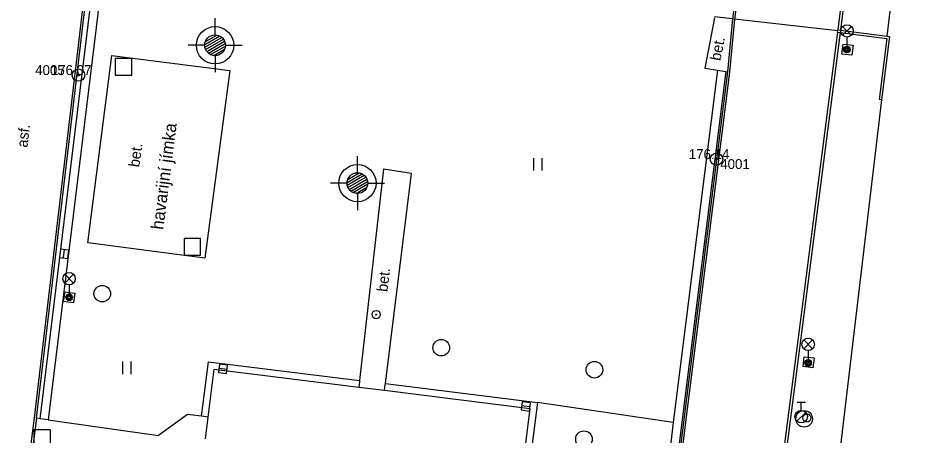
# Model space of a CAD drawing. Extents: x -540235 to -537963, y -1184915 to -1183660.
# Drawn here: x -540130.4 to -540075.6, y -1184027.1 to -1184001.9 of the extents above; entities that cross this region are included whole.
import ezdxf

# ---------------------------------------------------------------- set-up
doc = ezdxf.new("R2010")
doc.units = 0
for name, color, linetype in [('Vrstva 10', 7, 'Continuous'), ('Vrstva 11', 7, 'Continuous'), ('Vrstva 21', 7, 'Continuous'), ('Vrstva 22', 7, 'Continuous'), ('Vrstva 23', 7, 'Continuous'), ('Vrstva 25', 7, 'Continuous'), ('Vrstva 26', 7, 'Continuous'), ('Vrstva 27', 7, 'Continuous'), ('Vrstva 28', 7, 'Continuous'), ('Vrstva 33', 7, 'Continuous'), ('Vrstva 35', 7, 'Continuous'), ('Vrstva 36', 7, 'Continuous'), ('Vrstva 40', 7, 'Continuous'), ('Vrstva 41', 7, 'Continuous'), ('Vrstva 5', 7, 'Continuous'), ('Vrstva 7', 7, 'Continuous'), ('Vrstva 8', 7, 'Continuous')]:
    doc.layers.add(name, color=color, linetype=linetype)

msp = doc.modelspace()

# ---------------------------------------------------------------- linework, layer by layer
at = {"layer": 'Vrstva 10'}
for p, q in [((-540078.46, -1183982.89), (-540080.947, -1184002.636)), ((-540129.3, -1184026.075), (-540126.08, -1183998.755)), ((-540080.966, -1184002.785), (-540086.04, -1184042.215)), ((-540087.61, -1184005.175), (-540090.57, -1184028.685))]:
    msp.add_line(p, q, dxfattribs=at)
msp.add_lwpolyline([(-540085.41, -1183988), (-540087.303, -1184001.976), (-540087.61, -1184005.175)], dxfattribs=at)
at = {"layer": 'Vrstva 11'}
for p, q in [((-540129.419, -1184026.061), (-540126.213, -1183998.856)), ((-540129.092, -1184026.105), (-540125.768, -1183998.87)), ((-540125.272, -1183998.93), (-540128.597, -1184026.175)), ((-540080.428, -1183999.778), (-540080.798, -1184002.655)), ((-540080.818, -1184002.804), (-540085.892, -1184042.238)), ((-540126.21, -1184015.5), (-540124.76, -1184004.18)), ((-540124.76, -1184004.18), (-540117.65, -1184005.09)), ((-540117.65, -1184005.09), (-540119.15, -1184016.42)), ((-540088.203, -1184005.08), (-540090.879, -1184026.337)), ((-540087.709, -1184005.159), (-540090.669, -1184028.669)), ((-540087.491, -1184005.188), (-540090.451, -1184028.703)), ((-540108.36, -1184011.05), (-540109.813, -1184023.807)), ((-540106.68, -1184011.3), (-540108.36, -1184011.05)), ((-540108.25, -1184023.989), (-540106.68, -1184011.3)), ((-540119.15, -1184016.42), (-540126.21, -1184015.5)), ((-540119.356, -1184025.955), (-540118.93, -1184022.67)), ((-540118.93, -1184022.67), (-540109.813, -1184023.807)), ((-540108.25, -1184023.989), (-540099.08, -1184025.12)), ((-540099.08, -1184025.12), (-540099.851, -1184031.26)), ((-540129.936, -1184029.955), (-540129.419, -1184026.061)), ((-540129.3, -1184026.075), (-540129.817, -1184029.971)), ((-540128.597, -1184026.175), (-540121.94, -1184027.125)), ((-540090.879, -1184026.337), (-540091.163, -1184028.593))]:
    msp.add_line(p, q, dxfattribs=at)
for points in [[(-540086.777, -1183999.027), (-540087.183, -1184001.991), (-540087.491, -1184005.188)], [(-540088.4, -1184001.925), (-540088.98, -1184004.955), (-540088.203, -1184005.08), (-540087.709, -1184005.159), (-540087.61, -1184005.175)], [(-540080.701, -1184004.098), (-540080.629, -1184003.502), (-540080.033, -1184003.574), (-540080.105, -1184004.17), (-540080.701, -1184004.098)], [(-540127.58, -1184018.44), (-540126.987, -1184018.529), (-540127.076, -1184019.122), (-540127.669, -1184019.033), (-540127.58, -1184018.44)], [(-540083.051, -1184022.959), (-540082.979, -1184022.363), (-540082.383, -1184022.435), (-540082.455, -1184023.03), (-540083.051, -1184022.959)], [(-540109.813, -1184023.807), (-540109.82, -1184023.87), (-540109.86, -1184024.195)], [(-540108.3, -1184024.39), (-540108.26, -1184024.07), (-540108.25, -1184023.989)], [(-540118.952, -1184026.008), (-540119.356, -1184025.955), (-540120.19, -1184025.845), (-540121.94, -1184027.125)], [(-540128.597, -1184026.175), (-540129.092, -1184026.105), (-540129.3, -1184026.075)]]:
    msp.add_lwpolyline(points, dxfattribs=at)
at = {"layer": 'Vrstva 21'}
for centre, radius in [((-540126.77, -1184005.37), 0.375), ((-540126.77, -1184005.37), 0.05), ((-540088.27, -1184010.44), 0.375), ((-540088.27, -1184010.44), 0.05)]:
    msp.add_circle(centre, radius, dxfattribs=at)
at = {"layer": 'Vrstva 23'}
msp.add_line((-540090.879, -1184026.337), (-540099.08, -1184025.12), dxfattribs=at)
at = {"layer": 'Vrstva 25'}
for radius in [0.25, 0.0303]:
    msp.add_circle((-540108.81, -1184019.82), radius, dxfattribs=at)
at = {"layer": 'Vrstva 26'}
for points in [[(-540124.55, -1184005.372), (-540123.55, -1184005.372), (-540123.55, -1184004.372), (-540124.55, -1184004.372)], [(-540120.405, -1184016.232), (-540119.405, -1184016.232), (-540119.405, -1184015.232), (-540120.405, -1184015.232)], [(-540129.46, -1184027.775), (-540128.46, -1184027.775), (-540128.46, -1184026.775), (-540129.46, -1184026.775)]]:
    msp.add_lwpolyline(points, close=True, dxfattribs=at)
at = {"layer": 'Vrstva 27'}
for p, q in [((-540127.67, -1184016.398), (-540127.61, -1184015.902)), ((-540117.802, -1184023.131), (-540118.298, -1184023.069)), ((-540099.532, -1184025.391), (-540100.028, -1184025.329))]:
    msp.add_line(p, q, dxfattribs=at)
for points in [[(-540127.422, -1184016.428), (-540127.362, -1184015.932), (-540127.858, -1184015.872), (-540127.918, -1184016.368)], [(-540117.771, -1184022.883), (-540118.267, -1184022.821), (-540118.329, -1184023.317), (-540117.833, -1184023.379)], [(-540099.501, -1184025.143), (-540099.997, -1184025.081), (-540100.059, -1184025.577), (-540099.563, -1184025.639)]]:
    msp.add_lwpolyline(points, close=True, dxfattribs=at)
for centre in [(-540125.34, -1184018.56), (-540104.88, -1184021.82), (-540095.64, -1184023.15), (-540082.98, -1184026.11), (-540096.27, -1184027.34)]:
    msp.add_circle(centre, 0.5, dxfattribs=at)
at = {"layer": 'Vrstva 28'}
for p, q in [((-540083.41, -1184025.105), (-540082.91, -1184025.105)), ((-540083.16, -1184025.605), (-540083.16, -1184025.105)), ((-540083.418, -1184026.252), (-540082.888, -1184025.722))]:
    msp.add_line(p, q, dxfattribs=at)
for centre, radius in [((-540083.16, -1184025.98), 0.375), ((-540082.82, -1184026.06), 0.25)]:
    msp.add_circle(centre, radius, dxfattribs=at)
at = {"layer": 'Vrstva 33'}
for p, q in [((-540080.665, -1184002.97), (-540080.135, -1184002.44)), ((-540080.665, -1184002.44), (-540080.135, -1184002.97)), ((-540080.4, -1184003.08), (-540080.4, -1184003.83)), ((-540127.605, -1184017.92), (-540127.075, -1184017.39)), ((-540127.605, -1184017.39), (-540127.075, -1184017.92)), ((-540127.34, -1184018.03), (-540127.34, -1184018.78)), ((-540083.005, -1184021.88), (-540082.475, -1184021.35)), ((-540083.005, -1184021.35), (-540082.475, -1184021.88)), ((-540082.74, -1184021.99), (-540082.74, -1184022.74))]:
    msp.add_line(p, q, dxfattribs=at)
for centre, radius in [((-540080.4, -1184002.705), 0.375), ((-540080.4, -1184003.83), 0.2), ((-540080.4, -1184003.83), 0.1445), ((-540080.4, -1184003.83), 0.0876), ((-540127.34, -1184017.655), 0.375), ((-540127.34, -1184018.78), 0.2), ((-540127.34, -1184018.78), 0.1445), ((-540127.34, -1184018.78), 0.0876), ((-540082.74, -1184021.615), 0.375), ((-540082.74, -1184022.74), 0.2), ((-540082.74, -1184022.74), 0.1445), ((-540082.74, -1184022.74), 0.0876)]:
    msp.add_circle(centre, radius, dxfattribs=at)
at = {"layer": 'Vrstva 35'}
for p, q in [((-540118.53, -1184002.945), (-540118.53, -1184001.945)), ((-540119.112, -1184003.346), (-540118.433, -1184002.953)), ((-540119.153, -1184003.531), (-540118.252, -1184003.011)), ((-540119.143, -1184003.687), (-540118.122, -1184003.097)), ((-540119.101, -1184003.824), (-540118.024, -1184003.202)), ((-540119.03, -1184003.945), (-540117.956, -1184003.324)), ((-540118.93, -1184004.049), (-540117.915, -1184003.463)), ((-540119.155, -1184003.57), (-540120.155, -1184003.57)), ((-540118.798, -1184004.134), (-540117.908, -1184003.62)), ((-540118.613, -1184004.189), (-540117.953, -1184003.808)), ((-540117.905, -1184003.57), (-540116.905, -1184003.57)), ((-540118.53, -1184004.195), (-540118.53, -1184005.195)), ((-540109.94, -1184011.265), (-540109.94, -1184010.265)), ((-540110.563, -1184011.851), (-540109.662, -1184011.331)), ((-540110.553, -1184012.007), (-540109.532, -1184011.417)), ((-540110.522, -1184011.666), (-540109.843, -1184011.273)), ((-540110.511, -1184012.144), (-540109.434, -1184011.522)), ((-540110.44, -1184012.265), (-540109.366, -1184011.644)), ((-540110.565, -1184011.89), (-540111.565, -1184011.89)), ((-540110.34, -1184012.369), (-540109.325, -1184011.783)), ((-540110.208, -1184012.454), (-540109.318, -1184011.94)), ((-540110.023, -1184012.509), (-540109.363, -1184012.128)), ((-540109.315, -1184011.89), (-540108.315, -1184011.89)), ((-540109.94, -1184012.515), (-540109.94, -1184013.515))]:
    msp.add_line(p, q, dxfattribs=at)
for centre, radius in [((-540118.53, -1184003.57), 1.125), ((-540118.53, -1184003.57), 0.625), ((-540109.94, -1184011.89), 1.125), ((-540109.94, -1184011.89), 0.625)]:
    msp.add_circle(centre, radius, dxfattribs=at)
at = {"layer": 'Vrstva 36'}
for p, q in [((-540099.291, -1184011.125), (-540099.291, -1184010.375)), ((-540098.791, -1184011.125), (-540098.791, -1184010.375)), ((-540124.104, -1184023.409), (-540124.104, -1184022.659)), ((-540123.604, -1184023.409), (-540123.604, -1184022.659))]:
    msp.add_line(p, q, dxfattribs=at)
at = {"layer": 'Vrstva 5'}
for p, q in [((-540118.952, -1184026.008), (-540118.59, -1184023.11)), ((-540118.59, -1184023.11), (-540109.86, -1184024.195)), ((-540109.86, -1184024.195), (-540108.3, -1184024.39)), ((-540108.3, -1184024.39), (-540099.53, -1184025.48)), ((-540099.53, -1184025.48), (-540100.252, -1184031.209)), ((-540119.117, -1184027.324), (-540118.952, -1184026.008))]:
    msp.add_line(p, q, dxfattribs=at)
at = {"layer": 'Vrstva 7'}
for p, q in [((-540077.971, -1184003.016), (-540075.28, -1183980.14)), ((-540078.311, -1184006.864), (-540085.189, -1184064.922))]:
    msp.add_line(p, q, dxfattribs=at)
for points in [[(-540080.966, -1184002.785), (-540080.957, -1184002.71), (-540080.947, -1184002.636), (-540080.798, -1184002.655), (-540077.971, -1184003.016), (-540077.822, -1184003.035), (-540078.311, -1184006.864), (-540078.46, -1184006.845)], [(-540080.966, -1184002.785), (-540080.818, -1184002.804), (-540077.99, -1184003.165), (-540078.46, -1184006.845)]]:
    msp.add_lwpolyline(points, dxfattribs=at)
at = {"layer": 'Vrstva 8'}
msp.add_line((-540080.957, -1184002.71), (-540087.183, -1184001.991), dxfattribs=at)
msp.add_lwpolyline([(-540087.183, -1184001.991), (-540087.303, -1184001.976), (-540088.39, -1184001.85)], dxfattribs=at)

# ---------------------------------------------------------------- texts
at = {"layer": 'Vrstva 22'}
for s, p in [('176.07', (-540128.445, -1184005.37)), ('176.14', (-540089.945, -1184010.44))]:
    msp.add_text(s, height=0.6, dxfattribs=at).set_placement(p)
at = {"layer": 'Vrstva 23'}
for s, p in [('4005 ', (-540129.387, -1184005.37)), (' 4001', (-540088.27, -1184011.04))]:
    msp.add_text(s, height=0.6, dxfattribs=at).set_placement(p)
at = {"layer": 'Vrstva 40'}
for s, rotation, p in [('bet.', 79.16357, (-540088.032, -1184004.544)), ('asf.', 83.27799, (-540129.858, -1184009.766)), ('bet.', 82.17194, (-540123.11, -1184010.956)), ('bet.', 82.94678, (-540108.136, -1184018.477))]:
    msp.add_text(s, height=0.65, rotation=rotation, dxfattribs=at).set_placement(p)
at = {"layer": 'Vrstva 41'}
msp.add_text('havarijní jímka', height=0.75, rotation=82.70063, dxfattribs=at).set_placement((-540121.661, -1184014.729))

doc.saveas('drawing.dxf')
